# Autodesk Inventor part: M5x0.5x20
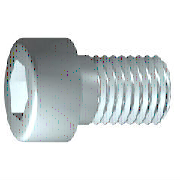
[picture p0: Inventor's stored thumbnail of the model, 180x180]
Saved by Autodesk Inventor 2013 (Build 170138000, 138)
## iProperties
IsCustomPart: 0
Company: 한국ATC센터
Created: 2014-07
Part Number: M5x0.5x20
Material: Steel, Mild
Description: 6각머리 태핑 나사
Document SubType Name: Modeling
Standard: KS B 1003
Designer: KYOUNG IL JANG
Standards Organization: KS
Language: ko-KR
Size Designation: M 5 x 20
Categories: <MemberInstance><Categories><Category DisplayName="조임쇠" InternalName="e4da775c-781d-43d5-af7c-5136215cf5a6" Mnemonic="FSTN"><Category DisplayName="볼트" InternalN
Density: 7.86 g/cm^3
Mass: 4.9629 g
Surface Area: 5.88237 cm^2
Volume: 0.631412 cm^3
Author: KYOUNG IL JANG
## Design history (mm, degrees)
sketch "스케치1"
  geometry: L1 (-1.167, 0)-(20, 0); L2 (20, 0)-(20, 2.5); L3 (20, 2.5)-(2, 2.5); L4 (2, 2.5)-(1.509, 2.5); L5 (1.509, 2.5)-(0, 2.5); L6 (0, 2.5)-(0, 4.25); L7 (0, 4.25)-(-5, 4.25); L8 (-5, 4.25)-(-5, 2.309); L9 (-5, 2.309)-(-2.5, 2.309); L10 (-2.5, 2.309)-(-1.167, 0); L11 (-10, 0)-(25, 0) reference; L12 (0, -0.85)-(0, 5.1) reference; L13 (2, 2.5)-(0, 2.5)
  constraints: 22 end point, 6 parallel, 2 collinear, 2 perpendicular, 1 horizontal, 1 point on line
  dimensions: "d1" = 18 distance from line of L3.end L2 (= GEL); "d2" = 0.49086 distance of L4.end L3.end (computed from GAL); "d3" = 5 distance between parallel lines of L8 L6 (= KOH); "d4" = 2.5 distance of L8.end L9.end (= INTI); "d5" = 60 deg angle of L10 L1; "d6" = 5 diameter of L3 L1 (= GD); "d7" = 5 diameter of L5 L1 (= BDM); "d8" = 4.6188 diameter of L9 L1 (= 1.1547 x SW); "d9" = 8.5 diameter of L7 L1 (= KOD); "d26" = 20 distance between parallel lines of L12 L2 (= NLG)
revolve "본체" sketch "스케치1" stored, may be unused: angle "d10" = 90 deg
sketch "스케치2"
  geometry: L1 (0, -5.95)-(0, 5.95) reference; L2 (-5.95, 0)-(5.95, 0) reference; L3 (2.309, 0)-(1.155, -2); L4 (1.155, -2)-(-1.155, -2); L5 (-1.155, -2)-(-2.309, 0); L6 (-2.309, 0)-(-1.155, 2); L7 (-1.155, 2)-(1.155, 2); L8 (1.155, 2)-(2.309, 0); 2 further points
  constraints: 12 end point, 1 coincident, 1 horizontal alignment, 1 point on line, 12 other
extrude "슬롯" join sketch "스케치2" stored distance "d11" = 10; taper "d12" = 0 deg
workplane "Work Plane1"
fillet "Fillet2" dims "d30" = 0.1 (= R)
body "Solid1"
fillet "모깎기1" dims "d17" = 0.5 (= RR)
feature "스레드" dims "d13" = 18 (= GEL), "d14" = 0
chamfer "모따기1" distance "d15" = 0.49076 (= -0.5 x SPD + 0.5 x GD); stored, may be unused: second distance "d16" = 0.49076 (= GUL), angle "d27" = 45 deg
other parameters: "GD" = 5 (= NND) [user parameter; used in 2 equation terms], "NLG" = 20 [user parameter; used in 1 equation term], "GEL" = 18 [user parameter; used in 2 equation terms], "KOD" = 8.5 [user parameter; used in 1 equation term], "KOH" = 5 [user parameter; used in 1 equation term], "INTI" = 2.5 [user parameter; used in 1 equation term], "GAL" = 0.49076 (= 0.61345 x PTC) [user parameter; used in 1 equation term], "GUL" = 0.49076 (= 0.61345 x PTC) [user parameter; used in 1 equation term], "BDM" = 5 (= NND) [user parameter; used in 1 equation term], "SW" = 4 [user parameter; used in 2 equation terms], "RR" = 0.5 [user parameter; used in 1 equation term], "SPD" = 4.01848 (= NND - 1.2269 x PTC) [user parameter; used in 1 equation term], "d19" = 0, "d28" = 0, "d29" = 0, "R" = 0.1 [user parameter; used in 1 equation term], "PHH" = 0.2 [user parameter], "GD1" = 4.01848 (= THREADDIA - 1.2269 x PTC) [user parameter], "THREADDIA" = 5 [user parameter; used in 1 equation term], "FAWI" = 45 deg [user parameter], "TPU" = 12.5 (computed from PTC) [user parameter], "PTC" = 0.8 [user parameter; used in 5 equation terms], "NND" = 5 [user parameter; used in 3 equation terms], "TOA" = 30 deg [user parameter], "E0" = 4.62 (= 1.155 x SW) [user parameter]
